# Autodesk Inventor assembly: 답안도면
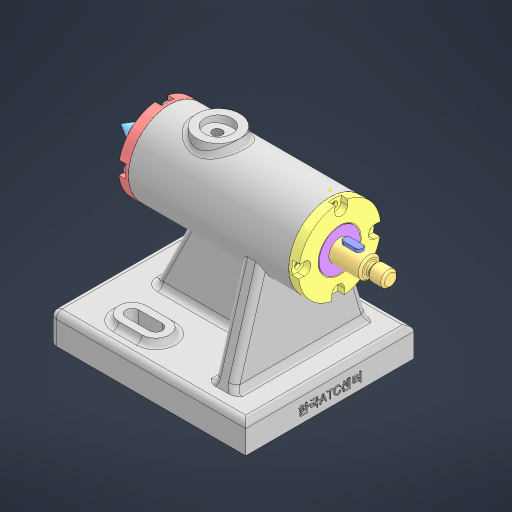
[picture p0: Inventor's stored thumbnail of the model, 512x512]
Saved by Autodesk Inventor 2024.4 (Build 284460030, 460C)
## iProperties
Created: 2026-09
Part Number: 답안도면
Document SubType Name: Assembly
Designer: user
Author: user
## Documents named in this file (12)
- C:\Users\user\Desktop\760903V1006\답안도면.iam
- C:\Users\user\Desktop\760903V1006\본체도면.ipt
- C:\Users\user\Desktop\760903V1006\가이드 부시\가이드 부시\가이드 부시.ipt
- C:\Users\user\Desktop\760903V1006\6각 구멍붙이 볼트 M3x8\6각 구멍붙이 볼트 M3x8\6각 구멍붙이 볼트 M3x8.ipt
- C:\Users\user\Desktop\760903V1006\슬리브\슬리브\슬리브.ipt
- C:\Users\user\Desktop\760903V1006\센터홀더\센터홀더\센터홀더.ipt
- C:\Users\user\Desktop\760903V1006\멈춤나사 M3\멈춤나사 M3\멈춤나사 M3.ipt
- C:\Users\user\Desktop\760903V1006\센터\센터\센터.ipt
- C:\Users\user\Desktop\760903V1006\커버\커버\커버.ipt
- C:\Users\user\Desktop\760903V1006\부시\부시\부시.ipt
- C:\Users\user\Desktop\760903V1006\나사축\나사축\나사축.ipt
- C:\Users\user\Desktop\760903V1006\평행 키 4x4x10\평행 키 4x4x10\평행 키 4x4x10.ipt
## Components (5 placed, 2 different names)
1. 가이드 부시:1 — 플러쉬:1
2. 6각 구멍붙이 볼트 M3x8:1
3. 6각 구멍붙이 볼트 M3x8:2
4. 6각 구멍붙이 볼트 M3x8:3
5. 6각 구멍붙이 볼트 M3x8:4
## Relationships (1: Flush 1)
- 플러쉬:1 [Flush]: 가이드 부시:1
